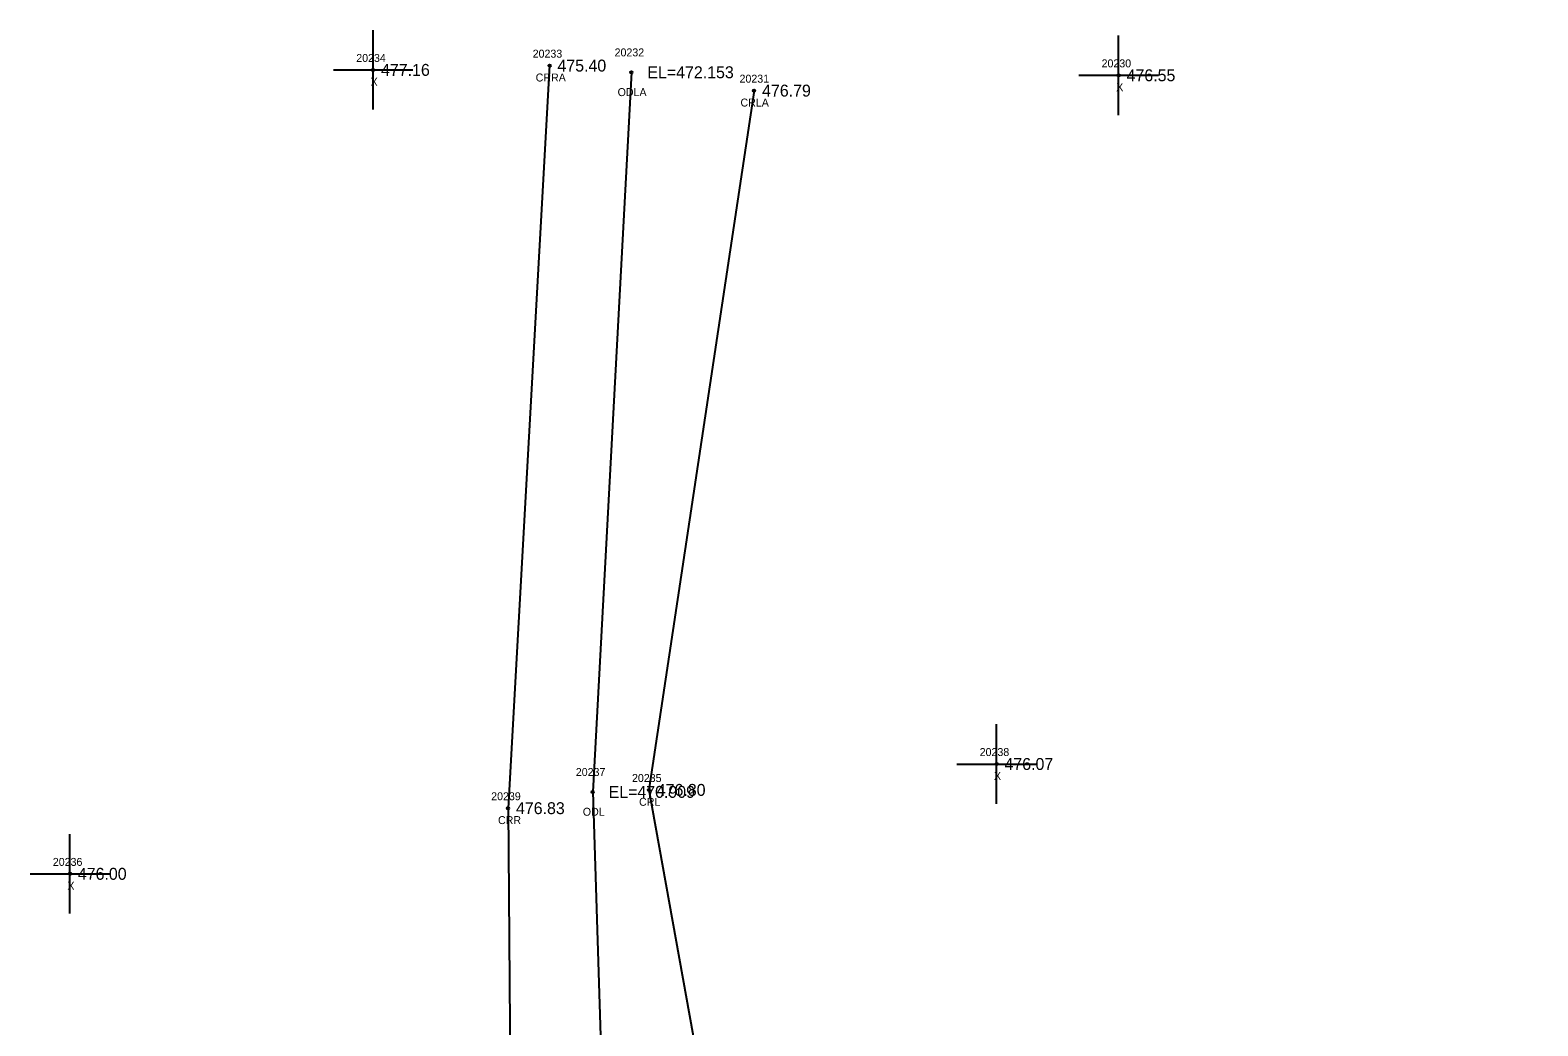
# Model space of a CAD drawing. Extents: x 1789565 to 1790548, y 909019 to 910194.
# Drawn here: x 1789851.1 to 1790040.8, y 910031.8 to 910157.1 of the extents above; entities that cross this region are included whole.
import ezdxf

# ---------------------------------------------------------------- set-up
doc = ezdxf.new("R2010")
doc.units = 0
for name, color, linetype in [('RD_EX_H2O', 7, 'Continuous'), ('RD_EX_H2O_txCode', 7, 'Continuous'), ('RD_EX_Misc', 7, 'Continuous'), ('RD_EX_Misc_txCode', 7, 'Continuous'), ('RD_EX_TX_H2O_ELEV', 7, 'Continuous'), ('RD_EX_TX_Misc_ELEV', 7, 'Continuous'), ('RD_SMD_Locator', 7, 'Continuous')]:
    doc.layers.add(name, color=color, linetype=linetype)

msp = doc.modelspace()

# ---------------------------------------------------------------- linework, layer by layer
at = {"layer": 'RD_EX_H2O'}
for points in [[(1789916.44, 910152.62), (1789911.22, 910059.17), (1789911.57, 910015.4), (1789913.25, 909950.04), (1789954.03, 909857.92), (1789966.14, 909807.85), (1790000.75, 909734.57), (1790025.55, 909650.06), (1790037.59, 909635.91)], [(1789926.75, 910151.78), (1789921.87, 910061.22), (1789923.33, 910015.8), (1789922.65, 909953.15), (1789957.79, 909859.65), (1789976.3, 909811.78), (1790009.05, 909737.59), (1790033.3, 909656.58), (1790043.84, 909640.77), (1790040.94, 909620.44), (1790068.41, 909598.88), (1790105.46, 909552.21), (1790128.28, 909493.4), (1790125.72, 909445.59), (1790167.31, 909436.17), (1790202.14, 909447.88), (1790216.41, 909437.36), (1790196.97, 909382.86), (1790209.47, 909371.8), (1790248.65, 909379.51), (1790333.47, 909404.65), (1790412.72, 909370.84), (1790438.82, 909377.48), (1790480.23, 909327.32)], [(1789942.19, 910149.47), (1789928.94, 910061.47), (1789937.03, 910016.56), (1789929.09, 909954.8), (1789962.46, 909861.74), (1789984.97, 909814.65), (1790017.82, 909740.15), (1790045.4, 909660.05), (1790055.69, 909646.96), (1790055.38, 909644.82), (1790053.69, 909634.91), (1790054.91, 909627.64), (1790075.55, 909607.72), (1790122.18, 909568.31), (1790142.55, 909490.86), (1790145.56, 909467.27), (1790204.21, 909464.64), (1790228.21, 909444.34), (1790208.83, 909385.44), (1790245.53, 909398.45), (1790340.56, 909420.98), (1790422.56, 909390.06), (1790444.95, 909390.88), (1790496, 909329.5)]]:
    msp.add_lwpolyline(points, dxfattribs=at)
at = {"layer": 'RD_EX_Misc'}
for p, q in [((1789894.24, 910147.08), (1789894.24, 910157.08)), ((1789988.06, 910146.4), (1789988.06, 910156.4)), ((1789889.24, 910152.08), (1789899.24, 910152.08)), ((1789983.06, 910151.4), (1789993.06, 910151.4)), ((1789972.69, 910059.73), (1789972.69, 910069.73)), ((1789967.69, 910064.73), (1789977.69, 910064.73)), ((1789856.09, 910045.91), (1789856.09, 910055.91)), ((1789851.09, 910050.91), (1789861.09, 910050.91))]:
    msp.add_line(p, q, dxfattribs=at)
at = {"layer": 'RD_SMD_Locator'}
for centre in [(1789916.44, 910152.62), (1789894.24, 910152.08), (1789926.75, 910151.78), (1789988.06, 910151.4), (1789942.19, 910149.47), (1789972.69, 910064.73), (1789928.94, 910061.47), (1789921.87, 910061.22), (1789911.22, 910059.17), (1789856.09, 910050.91)]:
    msp.add_circle(centre, 0.15, dxfattribs=at)

# ---------------------------------------------------------------- texts
at = {"layer": 'RD_EX_H2O_txCode'}
for s, p in [('20233', (1789914.32, 910153.62)), ('20232', (1789924.63, 910153.78)), ('CRRA', (1789914.7, 910150.62)), ('20231', (1789940.35, 910150.47)), ('ODLA', (1789925.01, 910148.78)), ('CRLA', (1789940.47, 910147.47)), ('20237', (1789919.75, 910063.22)), ('20235', (1789926.82, 910062.47)), ('20239', (1789909.1, 910060.17)), ('CRL', (1789927.71, 910059.47)), ('CRR', (1789909.96, 910057.17)), ('ODL', (1789920.63, 910058.22))]:
    msp.add_text(s, height=1, dxfattribs=at).set_placement(p)
at = {"layer": 'RD_EX_Misc_txCode'}
for s, p in [('20234', (1789892.12, 910153.08)), ('20230', (1789985.91, 910152.4)), ('X', (1789893.92, 910150.08)), ('X', (1789987.75, 910149.4)), ('20238', (1789970.57, 910065.73)), ('X', (1789972.37, 910062.73)), ('20236', (1789853.94, 910051.91)), ('X', (1789855.77, 910048.91))]:
    msp.add_text(s, height=1, dxfattribs=at).set_placement(p)
at = {"layer": 'RD_EX_TX_H2O_ELEV'}
for s, p in [('475.40', (1789917.44, 910151.87)), ('EL=472.153', (1789928.75, 910151.03)), ('476.79', (1789943.19, 910148.72)), ('EL=470.909', (1789923.87, 910060.47)), ('476.80', (1789929.94, 910060.72)), ('476.83', (1789912.22, 910058.42))]:
    msp.add_text(s, height=1.5, dxfattribs=at).set_placement(p)
at = {"layer": 'RD_EX_TX_Misc_ELEV'}
for s, p in [('477.16', (1789895.24, 910151.33)), ('476.55', (1789989.06, 910150.65)), ('476.07', (1789973.69, 910063.98)), ('476.00', (1789857.09, 910050.16))]:
    msp.add_text(s, height=1.5, dxfattribs=at).set_placement(p)

doc.saveas('drawing.dxf')
